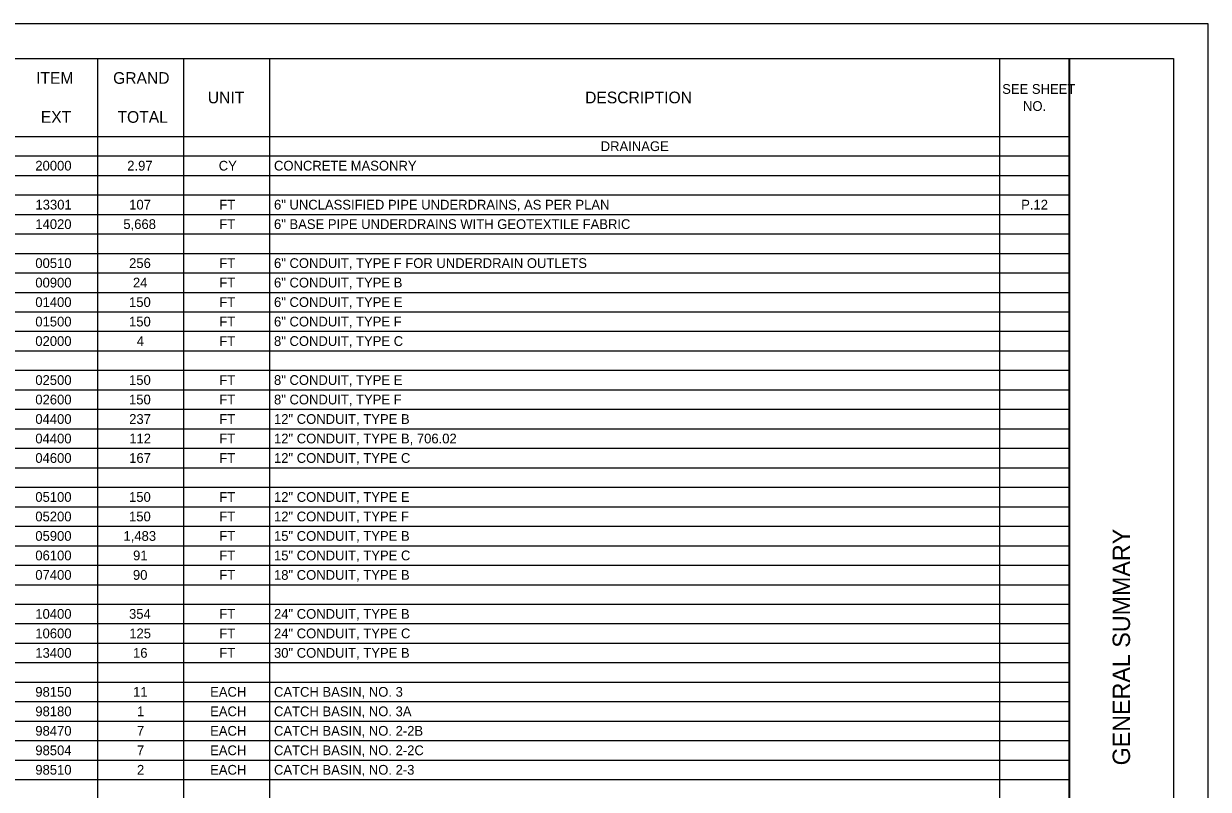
# Model space of a CAD drawing. Extents: x 0 to 34, y 0 to 22.
# Drawn here: x 16.98 to 34, y 11 to 22 of the extents above; entities that cross this region are included whole.
import ezdxf

# ---------------------------------------------------------------- set-up
doc = ezdxf.new("R2010")
doc.units = 0
for name, color, linetype in [('SH_Border', 7, 'Continuous'), ('SH_Cut_Line', 7, 'Continuous'), ('SH_Data', 7, 'Continuous'), ('SH_Text', 7, 'Continuous')]:
    doc.layers.add(name, color=color, linetype=linetype)

msp = doc.modelspace()

# ---------------------------------------------------------------- linework, layer by layer
at = {"layer": 'SH_Border'}
msp.add_line((32, 0.5), (32, 21.5), dxfattribs=at)
msp.add_lwpolyline([(1.5, 21.5), (33.5, 21.5), (33.5, 0.5), (1.5, 0.5)], close=True, dxfattribs=at)
at = {"layer": 'SH_Cut_Line'}
msp.add_lwpolyline([(0, 0), (34, 0), (34, 22), (0, 22)], close=True, dxfattribs=at)
at = {"layer": 'SH_Text'}
for p, q in [((1.5, 21.5), (32.004, 21.5)), ((18.036, 21.5), (18.036, 0.5)), ((19.272, 21.5), (19.272, 0.5)), ((20.507, 21.5), (20.507, 0.5)), ((30.999, 21.5), (30.999, 0.5)), ((32.004, 21.5), (32.004, 0.5)), ((1.5, 20.38), (32.004, 20.38)), ((1.5, 20.1), (32.004, 20.1)), ((1.5, 19.82), (32.004, 19.82)), ((1.5, 19.54), (32.004, 19.54)), ((1.5, 19.26), (32.004, 19.26)), ((1.5, 18.98), (32.004, 18.98)), ((1.5, 18.7), (32.004, 18.7)), ((1.5, 18.42), (32.004, 18.42)), ((1.5, 18.14), (32.004, 18.14)), ((1.5, 17.86), (32.004, 17.86)), ((1.5, 17.58), (32.004, 17.58)), ((1.5, 17.3), (32.004, 17.3)), ((1.5, 17.02), (32.004, 17.02)), ((1.5, 16.74), (32.004, 16.74)), ((1.5, 16.46), (32.004, 16.46)), ((1.5, 16.18), (32.004, 16.18)), ((1.5, 15.9), (32.004, 15.9)), ((1.5, 15.62), (32.004, 15.62)), ((1.5, 15.34), (32.004, 15.34)), ((1.5, 15.06), (32.004, 15.06)), ((1.5, 14.78), (32.004, 14.78)), ((1.5, 14.5), (32.004, 14.5)), ((1.5, 14.22), (32.004, 14.22)), ((1.5, 13.94), (32.004, 13.94)), ((1.5, 13.66), (32.004, 13.66)), ((1.5, 13.38), (32.004, 13.38)), ((1.5, 13.1), (32.004, 13.1)), ((1.5, 12.82), (32.004, 12.82)), ((1.5, 12.54), (32.004, 12.54)), ((1.5, 12.26), (32.004, 12.26)), ((1.5, 11.98), (32.004, 11.98)), ((1.5, 11.7), (32.004, 11.7)), ((1.5, 11.42), (32.004, 11.42)), ((1.5, 11.14), (32.004, 11.14))]:
    msp.add_line(p, q, dxfattribs=at)

# ---------------------------------------------------------------- texts
at = {"layer": 'SH_Data'}
msp.add_text('GENERAL SUMMARY', height=0.25, rotation=90, dxfattribs=at).set_placement((32.875, 11.344))
at = {"layer": 'SH_Text'}
for s, height, p in [('ITEM', 0.168, (17.154, 21.136)), ('GRAND', 0.168, (18.261, 21.136)), ('SEE SHEET ', 0.14, (31.038, 20.992)), ('UNIT', 0.168, (19.622, 20.856)), ('DESCRIPTION', 0.168, (25.044, 20.856)), ('NO.', 0.14, (31.337, 20.747)), ('EXT', 0.168, (17.222, 20.576)), ('TOTAL', 0.168, (18.324, 20.576)), ('DRAINAGE', 0.14, (25.268, 20.17)), ('20000', 0.14, (17.143, 19.89)), ('2.97', 0.14, (18.464, 19.89)), ('CY', 0.14, (19.779, 19.89)), ('CONCRETE MASONRY', 0.14, (20.573, 19.89)), ('13301', 0.14, (17.145, 19.33)), ('107', 0.14, (18.492, 19.33)), ('FT', 0.14, (19.786, 19.33)), ('6" UNCLASSIFIED PIPE UNDERDRAINS, AS PER PLAN', 0.14, (20.573, 19.33)), ('P.12', 0.14, (31.311, 19.33)), ('14020', 0.14, (17.143, 19.05)), ('5,668', 0.14, (18.408, 19.05)), ('FT', 0.14, (19.786, 19.05)), ('6" BASE PIPE UNDERDRAINS WITH GEOTEXTILE FABRIC', 0.14, (20.573, 19.05)), ('00510', 0.14, (17.143, 18.49)), ('256', 0.14, (18.491, 18.49)), ('FT', 0.14, (19.786, 18.49)), ('6" CONDUIT, TYPE F FOR UNDERDRAIN OUTLETS', 0.14, (20.573, 18.49)), ('00900', 0.14, (17.143, 18.21)), ('24', 0.14, (18.546, 18.21)), ('FT', 0.14, (19.786, 18.21)), ('6" CONDUIT, TYPE B', 0.14, (20.573, 18.21)), ('01400', 0.14, (17.143, 17.93)), ('150', 0.14, (18.49, 17.93)), ('FT', 0.14, (19.786, 17.93)), ('6" CONDUIT, TYPE E', 0.14, (20.573, 17.93)), ('01500', 0.14, (17.143, 17.65)), ('150', 0.14, (18.49, 17.65)), ('FT', 0.14, (19.786, 17.65)), ('6" CONDUIT, TYPE F', 0.14, (20.573, 17.65)), ('02000', 0.14, (17.143, 17.37)), ('4', 0.14, (18.601, 17.37)), ('FT', 0.14, (19.786, 17.37)), ('8" CONDUIT, TYPE C', 0.14, (20.573, 17.37)), ('02500', 0.14, (17.143, 16.81)), ('150', 0.14, (18.49, 16.81)), ('FT', 0.14, (19.786, 16.81)), ('8" CONDUIT, TYPE E', 0.14, (20.573, 16.81)), ('02600', 0.14, (17.143, 16.53)), ('150', 0.14, (18.49, 16.53)), ('FT', 0.14, (19.786, 16.53)), ('8" CONDUIT, TYPE F', 0.14, (20.573, 16.53)), ('04400', 0.14, (17.143, 16.25)), ('237', 0.14, (18.492, 16.25)), ('FT', 0.14, (19.786, 16.25)), ('12" CONDUIT, TYPE B', 0.14, (20.573, 16.25)), ('04400', 0.14, (17.143, 15.97)), ('112', 0.14, (18.493, 15.97)), ('FT', 0.14, (19.786, 15.97)), ('12" CONDUIT, TYPE B, 706.02', 0.14, (20.573, 15.97)), ('04600', 0.14, (17.143, 15.69)), ('167', 0.14, (18.492, 15.69)), ('FT', 0.14, (19.786, 15.69)), ('12" CONDUIT, TYPE C', 0.14, (20.573, 15.69)), ('05100', 0.14, (17.143, 15.13)), ('150', 0.14, (18.49, 15.13)), ('FT', 0.14, (19.786, 15.13)), ('12" CONDUIT, TYPE E', 0.14, (20.573, 15.13)), ('05200', 0.14, (17.143, 14.85)), ('150', 0.14, (18.49, 14.85)), ('FT', 0.14, (19.786, 14.85)), ('12" CONDUIT, TYPE F', 0.14, (20.573, 14.85)), ('05900', 0.14, (17.143, 14.57)), ('1,483', 0.14, (18.41, 14.57)), ('FT', 0.14, (19.786, 14.57)), ('15" CONDUIT, TYPE B', 0.14, (20.573, 14.57)), ('06100', 0.14, (17.143, 14.29)), ('91', 0.14, (18.548, 14.29)), ('FT', 0.14, (19.786, 14.29)), ('15" CONDUIT, TYPE C', 0.14, (20.573, 14.29)), ('07400', 0.14, (17.143, 14.01)), ('90', 0.14, (18.546, 14.01)), ('FT', 0.14, (19.786, 14.01)), ('18" CONDUIT, TYPE B', 0.14, (20.573, 14.01)), ('10400', 0.14, (17.143, 13.45)), ('354', 0.14, (18.49, 13.45)), ('FT', 0.14, (19.786, 13.45)), ('24" CONDUIT, TYPE B', 0.14, (20.573, 13.45)), ('10600', 0.14, (17.143, 13.17)), ('125', 0.14, (18.493, 13.17)), ('FT', 0.14, (19.786, 13.17)), ('24" CONDUIT, TYPE C', 0.14, (20.573, 13.17)), ('13400', 0.14, (17.143, 12.89)), ('16', 0.14, (18.547, 12.89)), ('FT', 0.14, (19.786, 12.89)), ('30" CONDUIT, TYPE B', 0.14, (20.573, 12.89)), ('98150', 0.14, (17.143, 12.33)), ('11', 0.14, (18.548, 12.33)), ('EACH', 0.14, (19.655, 12.33)), ('CATCH BASIN, NO. 3', 0.14, (20.573, 12.33)), ('98180', 0.14, (17.143, 12.05)), ('1', 0.14, (18.604, 12.05)), ('EACH', 0.14, (19.655, 12.05)), ('CATCH BASIN, NO. 3A', 0.14, (20.573, 12.05)), ('98470', 0.14, (17.143, 11.77)), ('7', 0.14, (18.603, 11.77)), ('EACH', 0.14, (19.655, 11.77)), ('CATCH BASIN, NO. 2-2B', 0.14, (20.573, 11.77)), ('98504', 0.14, (17.143, 11.49)), ('7', 0.14, (18.603, 11.49)), ('EACH', 0.14, (19.655, 11.49)), ('CATCH BASIN, NO. 2-2C', 0.14, (20.573, 11.49)), ('98510', 0.14, (17.143, 11.21)), ('2', 0.14, (18.604, 11.21)), ('EACH', 0.14, (19.655, 11.21)), ('CATCH BASIN, NO. 2-3', 0.14, (20.573, 11.21))]:
    msp.add_text(s, height=height, dxfattribs=at).set_placement(p)

doc.saveas('drawing.dxf')
